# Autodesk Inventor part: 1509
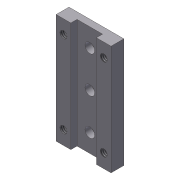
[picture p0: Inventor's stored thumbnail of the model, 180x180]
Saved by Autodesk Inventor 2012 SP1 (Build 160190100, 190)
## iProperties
Created: 2012-02
Part Number: 1509
Material: Aluminum-6061
Document SubType Name: Modeling
Designer: LACO
Density: 2.71 g/cm^3
Mass: 52.2942 g
Surface Area: 91.506 cm^2
Volume: 19.2967 cm^3
Author: LACO
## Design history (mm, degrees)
sketch "Sketch1"
  geometry: L1 (-19.05, 0)-(19.05, 0); L2 (19.05, 0)-(19.05, 76.2); L3 (19.05, 76.2)-(-19.05, 76.2); L4 (-19.05, 76.2)-(-19.05, 0); L5 (0, 0)-(0, 76.2)
  constraints: 10 end point, 3 parallel, 2 midpoint, 1 horizontal, 1 perpendicular, 1 other
  dimensions: "d0" = 76.2 distance of L1.end L2.end; "d1" = 38.1 distance between parallel lines of L2 L4
extrude "Extrusion1" new body sketch "Sketch1" distance "d2" = 4.572; taper "d3" = 0 deg
sketch "Sketch2"
  geometry: L1 (-19.05, 0)-(-19.05, 76.2) reference; L2 (19.05, 76.2)-(19.05, 0) reference; L3 (-19.05, 76.2)-(19.05, 76.2) reference; L4 (0, 0)-(0, 76.2); L5 (-19.05, 38.1)-(19.05, 38.1); 3 further points
  constraints: 5 midpoint, 4 end point, 2 point on line
  dimensions: "d5" = 25.4 distance from line of L5 point (0, 63.5); "d6" = 25.4 distance from line of point (0, 12.7) L5
hole "Hole1" sketch "Sketch2" at (0, 38.1), (0, 63.5), (0, 12.7) diameter "d7" = 6.7564; stored, may be unused: countersink angle "d11" = 82 deg, drill point angle "d13" = 118 deg; dims "d8" = 19.05, "d9" = 12.8778, "d10" = 6.35, "d12" = 25.4
sketch "Sketch3"
  geometry: L1 (19.05, 0)-(-19.05, 0) reference; L2 (-19.05, 76.2)-(19.05, 76.2) reference; L3 (-11.747, 71.12)-(-10.16, 71.12); L4 (-10.16, 71.12)-(-10.16, 5.08); L5 (-10.16, 5.08)-(-11.747, 5.08); L6 (-11.747, 5.08)-(-11.747, 71.12); L7 (10.16, 71.12)-(11.748, 71.12); L8 (11.748, 71.12)-(11.748, 5.08); L9 (11.748, 5.08)-(10.16, 5.08); L10 (10.16, 5.08)-(10.16, 71.12); L11 (0, 38.287)-(0, 76.2); A1 r 0.794 centre (-10.954, 71.12) between (-10.16, 71.12) and (-11.747, 71.12); A2 r 0.794 centre (10.954, 71.12) between (11.748, 71.12) and (10.16, 71.12); A3 r 0.794 centre (-10.954, 5.08) between (-11.747, 5.08) and (-10.16, 5.08); A4 r 0.794 centre (10.954, 5.08) between (10.16, 5.08) and (11.748, 5.08); 1 further point
  constraints: 18 end point, 8 point on circle, 5 midpoint, 4 centre point, 4 parallel, 2 collinear, 2 horizontal, 2 perpendicular, 2 other
  dimensions: "d14" = 20.32 distance between parallel lines of L10 L4; "d15" = 1.5875 distance between parallel lines of L4 L6; "d16" = 5.08 distance from line of L2 A1.centre; "d17" = 5.08 distance from line of L1 A3.centre
extrude "Extrusion2" cut sketch "Sketch3" distance "d18" = 1.27; taper "d19" = 0 deg
sketch "Sketch4"
  geometry: L1 (-19.05, 0)-(-19.05, 76.2) reference; L2 (19.05, 0)-(-19.05, 0) reference; L3 (19.05, 76.2)-(19.05, 0) reference; L4 (-19.05, 76.2)-(19.05, 76.2) reference; L5 (-8.89, 76.2)-(-8.89, 0); L6 (8.89, 76.2)-(8.89, 0); 1 further point
  constraints: 4 end point, 4 point on line, 2 perpendicular
  dimensions: "d20" = 10.16 distance between parallel lines of L5 L1; "d22" = 10.16 distance between parallel lines of L3 L6
extrude "Extrusion3" join sketch "Sketch4" distance "d23" = 4.318; taper "d24" = 0 deg
sketch "Sketch5"
  geometry: L1 (-19.05, 76.2)-(-8.89, 76.2) reference; L2 (-19.05, 0)-(-19.05, 76.2) reference; L3 (-8.89, 0)-(-19.05, 0) reference; L4 (-8.89, 76.2)-(-8.89, 0) reference; L5 (-13.97, 76.2)-(-13.97, 0); L6 (-19.05, 38.1)-(-8.89, 38.1); 3 further points
  constraints: 4 end point, 4 midpoint, 2 point on line
  dimensions: "d25" = 28.575 distance from line of point (-13.97, 66.675) L6; "d26" = 28.575 distance from line of point (-13.97, 9.525) L6
hole "Hole2" sketch "Sketch5" at (-13.97, 66.675), (-13.97, 9.525) diameter "d27" = 4.9784; stored, may be unused: countersink angle "d31" = 82 deg, drill point angle "d33" = 118 deg; dims "d28" = 3.81, "d29" = 12.8778, "d30" = 6.35, "d32" = 6.35
mirror "Mirror1"
body "Solid1"
